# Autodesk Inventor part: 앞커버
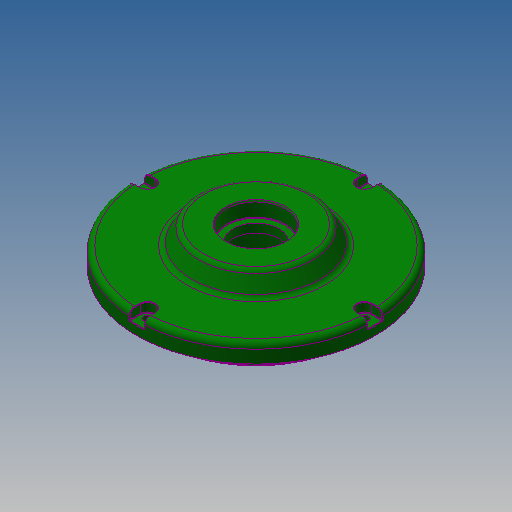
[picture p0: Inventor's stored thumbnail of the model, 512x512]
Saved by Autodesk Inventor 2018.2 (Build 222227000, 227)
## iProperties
Created: 2016-11
Part Number: 앞커버
Material: 알루미늄 6061
Document SubType Name: Modeling
Designer: mduedu
Density: 2.71 g/cm^3
Mass: 470.683 g
Surface Area: 413.208 cm^2
Volume: 173.684 cm^3
Appearance: 진녹색
Author: mduedu
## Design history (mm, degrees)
sketch "스케치1"
  geometry: L1 (30, -16)-(30, -30); L2 (30, -30)-(20, -35.774); L3 (20, -35.774)-(20, -65); L4 (20, -65)-(10, -65); L5 (10, -65)-(10, -53); L6 (10, -53)-(0, -53); L7 (0, -53)-(0, -23.5); L8 (0, 0)-(30, 0); L9 (14, -23.5)-(14, -20.5); L10 (14, -20.5)-(17, -20.5); L11 (17, -20.5)-(17, -12.5); L12 (0, -23.5)-(14, -23.5); L13 (21.7, -16)-(30, -16); L14 (21.7, -16)-(21.7, -12.5); L15 (21.7, -12.5)-(17, -12.5)
  constraints: 30 end point, 8 parallel, 5 perpendicular, 2 horizontal, 2 vertical alignment
  dimensions: "d0" = 10 distance of L5.end L6.end; "d2" = 10 distance of L3.end L4.end; "d3" = 10 distance between parallel lines of L1 L3; "d4" = 120 deg angle of L3 L2; "d6" = 60 diameter of L1.end L8; "d7" = 41 diameter of L10 L8; "d8" = 47 diameter of L12 L8; "d9" = 32 diameter of L13 L8; "d10" = 106 diameter of L6 L8; "d11" = 130 diameter of L4 L8; "d64" = 14 distance between parallel lines of L9 L7; "d65" = 3 distance of L9.end L10.end; "d66" = 8.3 distance of L13.start L1.start; "d67" = 25 diameter of L15 L8
revolve "회전1" sketch "스케치1" stored, may be unused: angle "d12" = 90 deg
fillet "모깎기1" dims "d13" = 1
fillet "모깎기2" dims "d14" = 3
chamfer "모따기1" distance "d15" = 1; stored, may be unused: second distance "d16" = 2, angle "d17" = 45 deg
fillet "모깎기3" dims "d18" = 0.3
chamfer "모따기2" distance "d36" = 0.8; stored, may be unused: second distance "d37" = 2, angle "d38" = 30 deg
sketch "스케치3"
  geometry: C1 r 65 at (0, 0) reference; A1 r 59 centre (0, 0) between (0, 59) and (59, 0); 2 further points
  constraints: 4 point on circle, 2 horizontal alignment, 2 vertical alignment, 1 centre point, 1 coincident
  dimensions: "d33" = 118 diameter of A1
sketch "스케치4"
  geometry: 4 further points
  constraints: 4 other
hole "구멍2" sketch "스케치4" at (0, 59), (-59, 0), (59, 0), (0, -59) diameter "d39" = 4.5; stored, may be unused: countersink angle "d43" = 90 deg, drill point angle "d45" = 0 deg; dims "d40" = 6, "d41" = 8, "d42" = 5, "d44" = 8
sketch "스케치6"
  geometry: L1 (-4, 5.877)-(-4, 0); L2 (4, 5.877)-(4, 0); A1 r 4 centre (0, 0) between (-2.712, 2.941) and (2.712, 2.941) reference; A2 r 65 centre (0, -59) between (-4, 5.877) and (4, 5.877) reference; 1 further point
  constraints: 4 end point, 4 point on circle, 2 tangent, 2 vertical
extrude "돌출2" cut sketch "스케치6" stored distance "d51" = 10; taper "d52" = 0 deg
fillet "모깎기5" dims "d56" = 0.3
fillet "모깎기6" dims "d57" = 0.3
sketch "스케치5"
  geometry: C1 r 30 at (0, 0); C2 r 47.5 at (0, 0); 1 further point
  constraints: 2 centre point, 2 coincident
  dimensions: "d46" = 60 diameter of C1; "d47" = 95 diameter of C2
extrude "돌출1" cut sketch "스케치5" distance "d48" = 10; taper "d49" = 0 deg
fillet "모깎기4" dims "d50" = 3
node "솔리드1"
pattern_circular "원형 패턴1" dims angle "d54" = 360 deg
pattern_circular "원형 패턴2" dims angle "d59" = 360 deg
pattern_circular "원형 패턴3" dims angle "d62" = 360 deg
